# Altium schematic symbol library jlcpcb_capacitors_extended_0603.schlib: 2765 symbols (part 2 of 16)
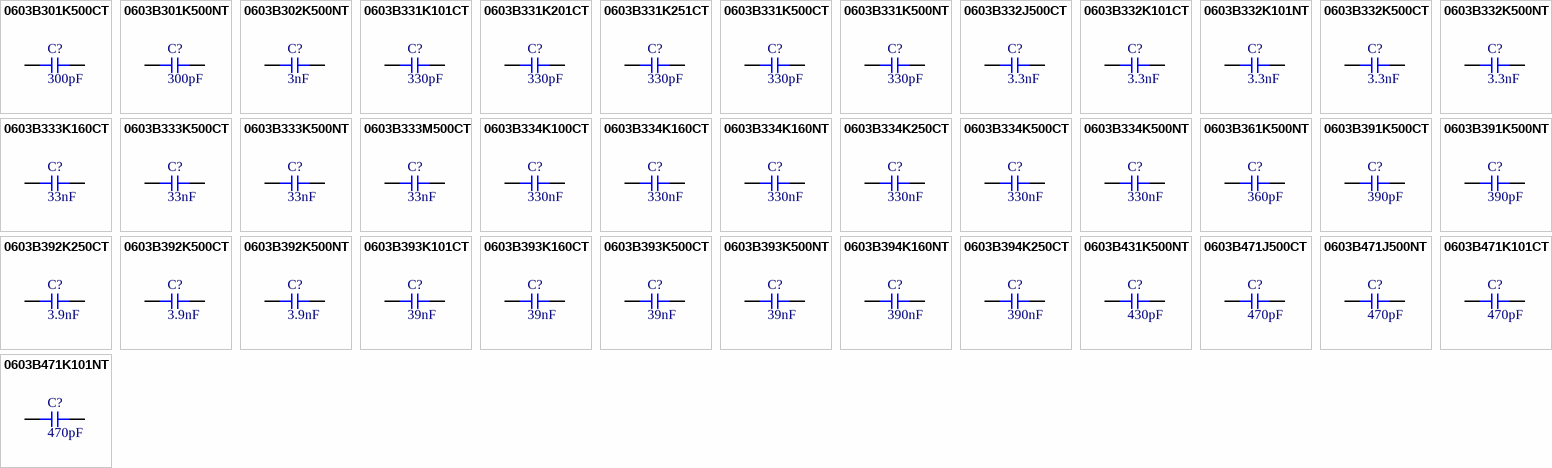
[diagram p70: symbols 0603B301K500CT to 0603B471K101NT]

## 0603B334K250CT
designator C?  Capacitance: 330nF  (hidden comment: *)
Capacitor, Ceramic (MLCC), 330nF, ±10%, 25V, X7R, ±10%, SMD 0603; Manufacturer: Walsin Tech Corp; Manufacturer Part Number: 0603B334K250CT
footprint CAP-0603 (0603 (1608M) Capacitor)
pins: 1, 2

## 0603B334K500CT
designator C?  Capacitance: 330nF  (hidden comment: *)
Capacitor, Ceramic (MLCC), 330nF, ±10%, 50V, X7R, ±10%, SMD 0603; Manufacturer: Walsin Tech Corp; Manufacturer Part Number: 0603B334K500CT
footprint CAP-0603 (0603 (1608M) Capacitor)
pins: 1, 2

## 0603B334K500NT
designator C?  Capacitance: 330nF  (hidden comment: *)
Capacitor, Ceramic (MLCC), 330nF, ±10%, 50V, X7R, ±10%, SMD 0603; Manufacturer: FH(Guangdong Fenghua Advanced Tech); Manufacturer Part Number: 0603B334K500NT
footprint CAP-0603 (0603 (1608M) Capacitor)
pins: 1, 2

## 0603B361K500NT
designator C?  Capacitance: 360pF  (hidden comment: *)
Capacitor, Ceramic (MLCC), 360pF, ±10%, 50V, X7R, ±10%, SMD 0603; Manufacturer: FH(Guangdong Fenghua Advanced Tech); Manufacturer Part Number: 0603B361K500NT
footprint CAP-0603 (0603 (1608M) Capacitor)
pins: 1, 2

## 0603B391K500CT
designator C?  Capacitance: 390pF  (hidden comment: *)
Capacitor, Ceramic (MLCC), 390pF, ±10%, 50V, X7R, ±10%, SMD 0603; Manufacturer: Walsin Tech Corp; Manufacturer Part Number: 0603B391K500CT
footprint CAP-0603 (0603 (1608M) Capacitor)
pins: 1, 2

## 0603B391K500NT
designator C?  Capacitance: 390pF  (hidden comment: *)
Capacitor, Ceramic (MLCC), 390pF, ±10%, 50V, X7R, ±10%, SMD 0603; Manufacturer: FH(Guangdong Fenghua Advanced Tech); Manufacturer Part Number: 0603B391K500NT
footprint CAP-0603 (0603 (1608M) Capacitor)
pins: 1, 2

## 0603B392K250CT
designator C?  Capacitance: 3.9nF  (hidden comment: *)
Capacitor, Ceramic (MLCC), 3.9nF, ±10%, 25V, X7R, ±10%, SMD 0603; Manufacturer: Walsin Tech Corp; Manufacturer Part Number: 0603B392K250CT
footprint CAP-0603 (0603 (1608M) Capacitor)
pins: 1, 2

## 0603B392K500CT
designator C?  Capacitance: 3.9nF  (hidden comment: *)
Capacitor, Ceramic (MLCC), 3.9nF, ±10%, 50V, X7R, ±10%, SMD 0603; Manufacturer: Walsin Tech Corp; Manufacturer Part Number: 0603B392K500CT
footprint CAP-0603 (0603 (1608M) Capacitor)
pins: 1, 2

## 0603B392K500NT
designator C?  Capacitance: 3.9nF  (hidden comment: *)
Capacitor, Ceramic (MLCC), 3.9nF, ±10%, 50V, X7R, ±10%, SMD 0603; Manufacturer: FH(Guangdong Fenghua Advanced Tech); Manufacturer Part Number: 0603B392K500NT
footprint CAP-0603 (0603 (1608M) Capacitor)
pins: 1, 2

## 0603B393K101CT
designator C?  Capacitance: 39nF  (hidden comment: *)
Capacitor, Ceramic (MLCC), 39nF, ±10%, 100V, X7R, ±10%, SMD 0603; Manufacturer: Walsin Tech Corp; Manufacturer Part Number: 0603B393K101CT
footprint CAP-0603 (0603 (1608M) Capacitor)
pins: 1, 2

## 0603B393K160CT
designator C?  Capacitance: 39nF  (hidden comment: *)
Capacitor, Ceramic (MLCC), 39nF, ±10%, 16V, X7R, ±10%, SMD 0603; Manufacturer: Walsin Tech Corp; Manufacturer Part Number: 0603B393K160CT
footprint CAP-0603 (0603 (1608M) Capacitor)
pins: 1, 2

## 0603B393K500CT
designator C?  Capacitance: 39nF  (hidden comment: *)
Capacitor, Ceramic (MLCC), 39nF, ±10%, 50V, X7R, ±10%, SMD 0603; Manufacturer: Walsin Tech Corp; Manufacturer Part Number: 0603B393K500CT
footprint CAP-0603 (0603 (1608M) Capacitor)
pins: 1, 2

## 0603B393K500NT
designator C?  Capacitance: 39nF  (hidden comment: *)
Capacitor, Ceramic (MLCC), 39nF, ±10%, 50V, X7R, ±10%, SMD 0603; Manufacturer: FH(Guangdong Fenghua Advanced Tech); Manufacturer Part Number: 0603B393K500NT
footprint CAP-0603 (0603 (1608M) Capacitor)
pins: 1, 2

## 0603B394K160NT
designator C?  Capacitance: 390nF  (hidden comment: *)
Capacitor, Ceramic (MLCC), 390nF, ±10%, 16V, ±10%, SMD 0603; Manufacturer: FH(Guangdong Fenghua Advanced Tech); Manufacturer Part Number: 0603B394K160NT
footprint CAP-0603 (0603 (1608M) Capacitor)
pins: 1, 2

## 0603B394K250CT
designator C?  Capacitance: 390nF  (hidden comment: *)
Capacitor, Ceramic (MLCC), 390nF, ±10%, 25V, X7R, ±10%, SMD 0603; Manufacturer: Walsin Tech Corp; Manufacturer Part Number: 0603B394K250CT
footprint CAP-0603 (0603 (1608M) Capacitor)
pins: 1, 2

## 0603B431K500NT
designator C?  Capacitance: 430pF  (hidden comment: *)
Capacitor, Ceramic (MLCC), 430pF, ±10%, 50V, X7R, ±10%, SMD 0603; Manufacturer: FH(Guangdong Fenghua Advanced Tech); Manufacturer Part Number: 0603B431K500NT
footprint CAP-0603 (0603 (1608M) Capacitor)
pins: 1, 2

## 0603B471J500CT
designator C?  Capacitance: 470pF  (hidden comment: *)
Capacitor, Ceramic (MLCC), 470pF, ±5%, 50V, X7R, ±5%, SMD 0603; Manufacturer: Walsin Tech Corp; Manufacturer Part Number: 0603B471J500CT
footprint CAP-0603 (0603 (1608M) Capacitor)
pins: 1, 2

## 0603B471J500NT
designator C?  Capacitance: 470pF  (hidden comment: *)
Capacitor, Ceramic (MLCC), 470pF, ±5%, 50V, X7R, ±5%, SMD 0603; Manufacturer: FH(Guangdong Fenghua Advanced Tech); Manufacturer Part Number: 0603B471J500NT
footprint CAP-0603 (0603 (1608M) Capacitor)
pins: 1, 2

## 0603B471K101CT
designator C?  Capacitance: 470pF  (hidden comment: *)
Capacitor, Ceramic (MLCC), 470pF, ±10%, 100V, X7R, ±10%, SMD 0603; Manufacturer: Walsin Tech Corp; Manufacturer Part Number: 0603B471K101CT
footprint CAP-0603 (0603 (1608M) Capacitor)
pins: 1, 2

## 0603B471K101NT
designator C?  Capacitance: 470pF  (hidden comment: *)
Capacitor, Ceramic (MLCC), 470pF, ±10%, 100V, X7R, ±10%, SMD 0603; Manufacturer: FH(Guangdong Fenghua Advanced Tech); Manufacturer Part Number: 0603B471K101NT
footprint CAP-0603 (0603 (1608M) Capacitor)
pins: 1, 2

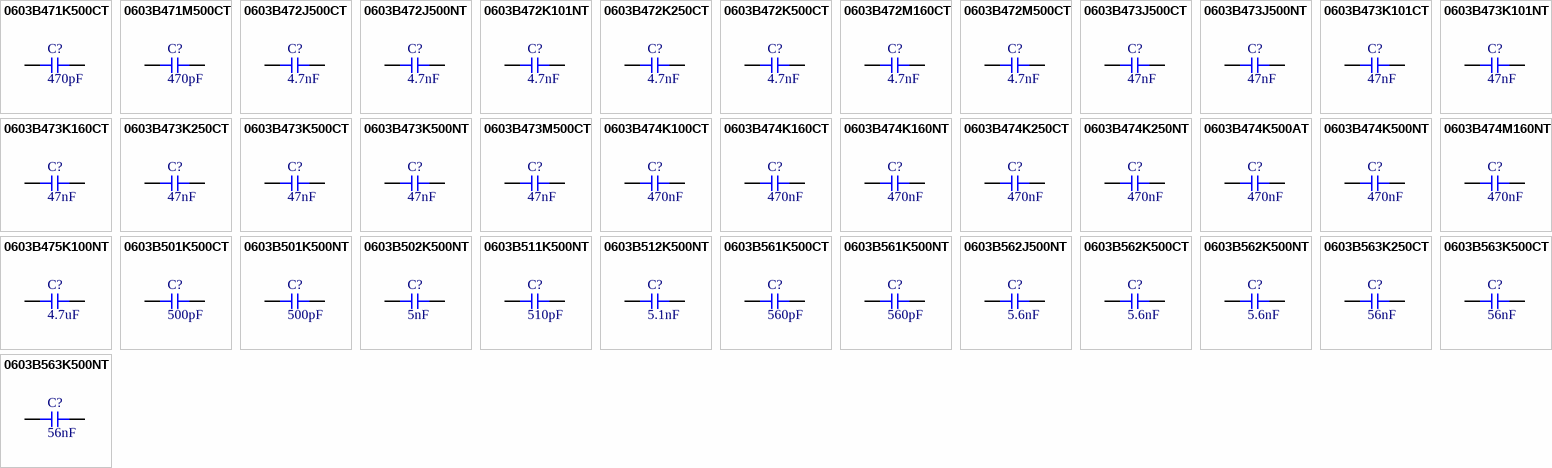
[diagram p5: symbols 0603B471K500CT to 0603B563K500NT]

## 0603B471K500CT
designator C?  Capacitance: 470pF  (hidden comment: *)
Capacitor, Ceramic (MLCC), 470pF, ±10%, 50V, X7R, ±10%, SMD 0603; Manufacturer: Walsin Tech Corp; Manufacturer Part Number: 0603B471K500CT
footprint CAP-0603 (0603 (1608M) Capacitor)
pins: 1, 2

## 0603B471M500CT
designator C?  Capacitance: 470pF  (hidden comment: *)
Capacitor, Ceramic (MLCC), 470pF, ±20%, 50V, X7R, ±20%, SMD 0603; Manufacturer: Walsin Tech Corp; Manufacturer Part Number: 0603B471M500CT
footprint CAP-0603 (0603 (1608M) Capacitor)
pins: 1, 2

## 0603B472J500CT
designator C?  Capacitance: 4.7nF  (hidden comment: *)
Capacitor, Ceramic (MLCC), 4.7nF, ±5%, 50V, X7R, ±5%, SMD 0603; Manufacturer: Walsin Tech Corp; Manufacturer Part Number: 0603B472J500CT
footprint CAP-0603 (0603 (1608M) Capacitor)
pins: 1, 2

## 0603B472J500NT
designator C?  Capacitance: 4.7nF  (hidden comment: *)
Capacitor, Ceramic (MLCC), 4.7nF, ±5%, 50V, X7R, ±5%, SMD 0603; Manufacturer: FH(Guangdong Fenghua Advanced Tech); Manufacturer Part Number: 0603B472J500NT
footprint CAP-0603 (0603 (1608M) Capacitor)
pins: 1, 2

## 0603B472K101NT
designator C?  Capacitance: 4.7nF  (hidden comment: *)
Capacitor, Ceramic (MLCC), 4.7nF, ±10%, 100V, X7R, ±10%, SMD 0603; Manufacturer: FH(Guangdong Fenghua Advanced Tech); Manufacturer Part Number: 0603B472K101NT
footprint CAP-0603 (0603 (1608M) Capacitor)
pins: 1, 2

## 0603B472K250CT
designator C?  Capacitance: 4.7nF  (hidden comment: *)
Capacitor, Ceramic (MLCC), 4.7nF, ±10%, 25V, X7R, ±10%, SMD 0603; Manufacturer: Walsin Tech Corp; Manufacturer Part Number: 0603B472K250CT
footprint CAP-0603 (0603 (1608M) Capacitor)
pins: 1, 2

## 0603B472K500CT
designator C?  Capacitance: 4.7nF  (hidden comment: *)
Capacitor, Ceramic (MLCC), 4.7nF, ±10%, 50V, X7R, ±10%, SMD 0603; Manufacturer: Walsin Tech Corp; Manufacturer Part Number: 0603B472K500CT
footprint CAP-0603 (0603 (1608M) Capacitor)
pins: 1, 2

## 0603B472M160CT
designator C?  Capacitance: 4.7nF  (hidden comment: *)
Capacitor, Ceramic (MLCC), 4.7nF, ±20%, 16V, X7R, ±20%, SMD 0603; Manufacturer: Walsin Tech Corp; Manufacturer Part Number: 0603B472M160CT
footprint CAP-0603 (0603 (1608M) Capacitor)
pins: 1, 2

## 0603B472M500CT
designator C?  Capacitance: 4.7nF  (hidden comment: *)
Capacitor, Ceramic (MLCC), 4.7nF, ±20%, 50V, X7R, ±20%, SMD 0603; Manufacturer: Walsin Tech Corp; Manufacturer Part Number: 0603B472M500CT
footprint CAP-0603 (0603 (1608M) Capacitor)
pins: 1, 2

## 0603B473J500CT
designator C?  Capacitance: 47nF  (hidden comment: *)
Capacitor, Ceramic (MLCC), 47nF, ±5%, 50V, X7R, ±5%, SMD 0603; Manufacturer: Walsin Tech Corp; Manufacturer Part Number: 0603B473J500CT
footprint CAP-0603 (0603 (1608M) Capacitor)
pins: 1, 2

## 0603B473J500NT
designator C?  Capacitance: 47nF  (hidden comment: *)
Capacitor, Ceramic (MLCC), 47nF, ±5%, 50V, X7R, ±5%, SMD 0603; Manufacturer: FH(Guangdong Fenghua Advanced Tech); Manufacturer Part Number: 0603B473J500NT
footprint CAP-0603 (0603 (1608M) Capacitor)
pins: 1, 2

## 0603B473K101CT
designator C?  Capacitance: 47nF  (hidden comment: *)
Capacitor, Ceramic (MLCC), 47nF, ±10%, 100V, X7R, ±10%, SMD 0603; Manufacturer: Walsin Tech Corp; Manufacturer Part Number: 0603B473K101CT
footprint CAP-0603 (0603 (1608M) Capacitor)
pins: 1, 2

## 0603B473K101NT
designator C?  Capacitance: 47nF  (hidden comment: *)
Capacitor, Ceramic (MLCC), 47nF, ±10%, 100V, X7R, ±10%, SMD 0603; Manufacturer: FH(Guangdong Fenghua Advanced Tech); Manufacturer Part Number: 0603B473K101NT
footprint CAP-0603 (0603 (1608M) Capacitor)
pins: 1, 2

## 0603B473K160CT
designator C?  Capacitance: 47nF  (hidden comment: *)
Capacitor, Ceramic (MLCC), 47nF, ±10%, 16V, X7R, ±10%, SMD 0603; Manufacturer: Walsin Tech Corp; Manufacturer Part Number: 0603B473K160CT
footprint CAP-0603 (0603 (1608M) Capacitor)
pins: 1, 2

## 0603B473K250CT
designator C?  Capacitance: 47nF  (hidden comment: *)
Capacitor, Ceramic (MLCC), 47nF, ±10%, 25V, X7R, ±10%, SMD 0603; Manufacturer: Walsin Tech Corp; Manufacturer Part Number: 0603B473K250CT
footprint CAP-0603 (0603 (1608M) Capacitor)
pins: 1, 2

## 0603B473K500CT
designator C?  Capacitance: 47nF  (hidden comment: *)
Capacitor, Ceramic (MLCC), 47nF, ±10%, 50V, X7R, ±10%, SMD 0603; Manufacturer: Walsin Tech Corp; Manufacturer Part Number: 0603B473K500CT
footprint CAP-0603 (0603 (1608M) Capacitor)
pins: 1, 2

## 0603B473K500NT
designator C?  Capacitance: 47nF  (hidden comment: *)
Capacitor, Ceramic (MLCC), 47nF, ±10%, 50V, X7R, ±10%, SMD 0603; Manufacturer: FH(Guangdong Fenghua Advanced Tech); Manufacturer Part Number: 0603B473K500NT
footprint CAP-0603 (0603 (1608M) Capacitor)
pins: 1, 2

## 0603B473M500CT
designator C?  Capacitance: 47nF  (hidden comment: *)
Capacitor, Ceramic (MLCC), 47nF, ±20%, 50V, X7R, ±20%, SMD 0603; Manufacturer: Walsin Tech Corp; Manufacturer Part Number: 0603B473M500CT
footprint CAP-0603 (0603 (1608M) Capacitor)
pins: 1, 2

## 0603B474K100CT
designator C?  Capacitance: 470nF  (hidden comment: *)
Capacitor, Ceramic (MLCC), 470nF, ±10%, 10V, X7R, ±10%, SMD 0603; Manufacturer: Walsin Tech Corp; Manufacturer Part Number: 0603B474K100CT
footprint CAP-0603 (0603 (1608M) Capacitor)
pins: 1, 2

## 0603B474K160CT
designator C?  Capacitance: 470nF  (hidden comment: *)
Capacitor, Ceramic (MLCC), 470nF, ±10%, 16V, X7R, ±10%, SMD 0603; Manufacturer: Walsin Tech Corp; Manufacturer Part Number: 0603B474K160CT
footprint CAP-0603 (0603 (1608M) Capacitor)
pins: 1, 2

## 0603B474K160NT
designator C?  Capacitance: 470nF  (hidden comment: *)
Capacitor, Ceramic (MLCC), 470nF, ±10%, 16V, X7R, ±10%, SMD 0603; Manufacturer: FH(Guangdong Fenghua Advanced Tech); Manufacturer Part Number: 0603B474K160NT
footprint CAP-0603 (0603 (1608M) Capacitor)
pins: 1, 2

## 0603B474K250CT
designator C?  Capacitance: 470nF  (hidden comment: *)
Capacitor, Ceramic (MLCC), 470nF, ±10%, 25V, X7R, ±10%, SMD 0603; Manufacturer: Walsin Tech Corp; Manufacturer Part Number: 0603B474K250CT
footprint CAP-0603 (0603 (1608M) Capacitor)
pins: 1, 2

## 0603B474K250NT
designator C?  Capacitance: 470nF  (hidden comment: *)
Capacitor, Ceramic (MLCC), 470nF, ±10%, 25V, X7R, ±10%, SMD 0603; Manufacturer: FH(Guangdong Fenghua Advanced Tech); Manufacturer Part Number: 0603B474K250NT
footprint CAP-0603 (0603 (1608M) Capacitor)
pins: 1, 2

## 0603B474K500AT
designator C?  Capacitance: 470nF  (hidden comment: *)
Capacitor, Ceramic (MLCC), 470nF, ±10%, 50V, ±10%, SMD 0603; Manufacturer: FH(Guangdong Fenghua Advanced Tech); Manufacturer Part Number: 0603B474K500AT
footprint CAP-0603 (0603 (1608M) Capacitor)
pins: 1, 2

## 0603B474K500NT
designator C?  Capacitance: 470nF  (hidden comment: *)
Capacitor, Ceramic (MLCC), 470nF, ±10%, 50V, X7R, ±10%, SMD 0603; Manufacturer: FH(Guangdong Fenghua Advanced Tech); Manufacturer Part Number: 0603B474K500NT
footprint CAP-0603 (0603 (1608M) Capacitor)
pins: 1, 2

## 0603B474M160NT
designator C?  Capacitance: 470nF  (hidden comment: *)
Capacitor, Ceramic (MLCC), 470nF, ±20%, 16V, X7R, ±20%, SMD 0603; Manufacturer: FH(Guangdong Fenghua Advanced Tech); Manufacturer Part Number: 0603B474M160NT
footprint CAP-0603 (0603 (1608M) Capacitor)
pins: 1, 2

## 0603B475K100NT
designator C?  Capacitance: 4.7uF  (hidden comment: *)
Capacitor, Ceramic (MLCC), 4.7uF, ±10%, 10V, X7R, ±10%, SMD 0603; Manufacturer: FH(Guangdong Fenghua Advanced Tech); Manufacturer Part Number: 0603B475K100NT
footprint CAP-0603 (0603 (1608M) Capacitor)
pins: 1, 2

## 0603B501K500CT
designator C?  Capacitance: 500pF  (hidden comment: *)
Capacitor, Ceramic (MLCC), 500pF, ±10%, 50V, X7R, ±10%, SMD 0603; Manufacturer: Walsin Tech Corp; Manufacturer Part Number: 0603B501K500CT
footprint CAP-0603 (0603 (1608M) Capacitor)
pins: 1, 2

## 0603B501K500NT
designator C?  Capacitance: 500pF  (hidden comment: *)
Capacitor, Ceramic (MLCC), 500pF, ±10%, 50V, X7R, ±10%, SMD 0603; Manufacturer: FH(Guangdong Fenghua Advanced Tech); Manufacturer Part Number: 0603B501K500NT
footprint CAP-0603 (0603 (1608M) Capacitor)
pins: 1, 2

## 0603B502K500NT
designator C?  Capacitance: 5nF  (hidden comment: *)
Capacitor, Ceramic (MLCC), 5nF, ±10%, 50V, X7R, ±10%, SMD 0603; Manufacturer: FH(Guangdong Fenghua Advanced Tech); Manufacturer Part Number: 0603B502K500NT
footprint CAP-0603 (0603 (1608M) Capacitor)
pins: 1, 2

## 0603B511K500NT
designator C?  Capacitance: 510pF  (hidden comment: *)
Capacitor, Ceramic (MLCC), 510pF, ±10%, 50V, X7R, ±10%, SMD 0603; Manufacturer: FH(Guangdong Fenghua Advanced Tech); Manufacturer Part Number: 0603B511K500NT
footprint CAP-0603 (0603 (1608M) Capacitor)
pins: 1, 2

## 0603B512K500NT
designator C?  Capacitance: 5.1nF  (hidden comment: *)
Capacitor, Ceramic (MLCC), 5.1nF, ±10%, 50V, X7R, ±10%, SMD 0603; Manufacturer: FH(Guangdong Fenghua Advanced Tech); Manufacturer Part Number: 0603B512K500NT
footprint CAP-0603 (0603 (1608M) Capacitor)
pins: 1, 2

## 0603B561K500CT
designator C?  Capacitance: 560pF  (hidden comment: *)
Capacitor, Ceramic (MLCC), 560pF, ±10%, 50V, X7R, ±10%, SMD 0603; Manufacturer: Walsin Tech Corp; Manufacturer Part Number: 0603B561K500CT
footprint CAP-0603 (0603 (1608M) Capacitor)
pins: 1, 2

## 0603B561K500NT
designator C?  Capacitance: 560pF  (hidden comment: *)
Capacitor, Ceramic (MLCC), 560pF, ±10%, 50V, X7R, ±10%, SMD 0603; Manufacturer: FH(Guangdong Fenghua Advanced Tech); Manufacturer Part Number: 0603B561K500NT
footprint CAP-0603 (0603 (1608M) Capacitor)
pins: 1, 2

## 0603B562J500NT
designator C?  Capacitance: 5.6nF  (hidden comment: *)
Capacitor, Ceramic (MLCC), 5.6nF, ±5%, 50V, X7R, ±5%, SMD 0603; Manufacturer: FH(Guangdong Fenghua Advanced Tech); Manufacturer Part Number: 0603B562J500NT
footprint CAP-0603 (0603 (1608M) Capacitor)
pins: 1, 2

## 0603B562K500CT
designator C?  Capacitance: 5.6nF  (hidden comment: *)
Capacitor, Ceramic (MLCC), 5.6nF, ±10%, 50V, X7R, ±10%, SMD 0603; Manufacturer: Walsin Tech Corp; Manufacturer Part Number: 0603B562K500CT
footprint CAP-0603 (0603 (1608M) Capacitor)
pins: 1, 2

## 0603B562K500NT
designator C?  Capacitance: 5.6nF  (hidden comment: *)
Capacitor, Ceramic (MLCC), 5.6nF, ±10%, 50V, X7R, ±10%, SMD 0603; Manufacturer: FH(Guangdong Fenghua Advanced Tech); Manufacturer Part Number: 0603B562K500NT
footprint CAP-0603 (0603 (1608M) Capacitor)
pins: 1, 2

## 0603B563K250CT
designator C?  Capacitance: 56nF  (hidden comment: *)
Capacitor, Ceramic (MLCC), 56nF, ±10%, 25V, X7R, ±10%, SMD 0603; Manufacturer: Walsin Tech Corp; Manufacturer Part Number: 0603B563K250CT
footprint CAP-0603 (0603 (1608M) Capacitor)
pins: 1, 2

## 0603B563K500CT
designator C?  Capacitance: 56nF  (hidden comment: *)
Capacitor, Ceramic (MLCC), 56nF, ±10%, 50V, X7R, ±10%, SMD 0603; Manufacturer: Walsin Tech Corp; Manufacturer Part Number: 0603B563K500CT
footprint CAP-0603 (0603 (1608M) Capacitor)
pins: 1, 2

## 0603B563K500NT
designator C?  Capacitance: 56nF  (hidden comment: *)
Capacitor, Ceramic (MLCC), 56nF, ±10%, 50V, X7R, ±10%, SMD 0603; Manufacturer: FH(Guangdong Fenghua Advanced Tech); Manufacturer Part Number: 0603B563K500NT
footprint CAP-0603 (0603 (1608M) Capacitor)
pins: 1, 2

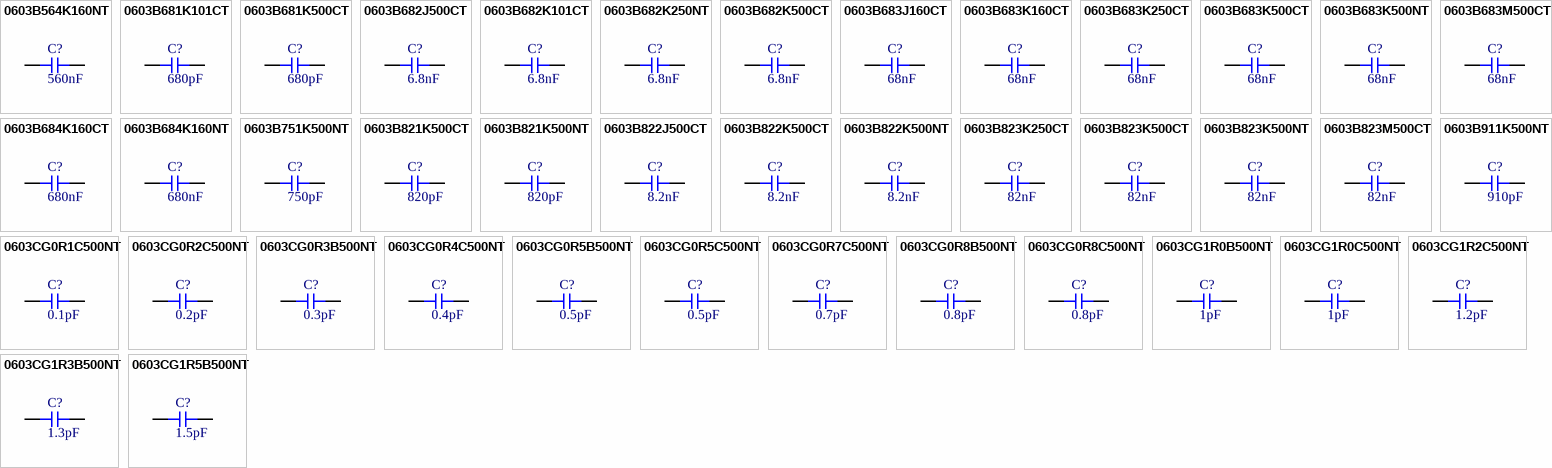
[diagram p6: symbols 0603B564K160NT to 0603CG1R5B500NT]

## 0603B564K160NT
designator C?  Capacitance: 560nF  (hidden comment: *)
Capacitor, Ceramic (MLCC), 560nF, ±10%, 16V, ±10%, SMD 0603; Manufacturer: FH(Guangdong Fenghua Advanced Tech); Manufacturer Part Number: 0603B564K160NT
footprint CAP-0603 (0603 (1608M) Capacitor)
pins: 1, 2

## 0603B681K101CT
designator C?  Capacitance: 680pF  (hidden comment: *)
Capacitor, Ceramic (MLCC), 680pF, ±10%, 100V, X7R, ±10%, SMD 0603; Manufacturer: Walsin Tech Corp; Manufacturer Part Number: 0603B681K101CT
footprint CAP-0603 (0603 (1608M) Capacitor)
pins: 1, 2

## 0603B681K500CT
designator C?  Capacitance: 680pF  (hidden comment: *)
Capacitor, Ceramic (MLCC), 680pF, ±10%, 50V, X7R, ±10%, SMD 0603; Manufacturer: Walsin Tech Corp; Manufacturer Part Number: 0603B681K500CT
footprint CAP-0603 (0603 (1608M) Capacitor)
pins: 1, 2

## 0603B682J500CT
designator C?  Capacitance: 6.8nF  (hidden comment: *)
Capacitor, Ceramic (MLCC), 6.8nF, ±5%, 50V, X7R, ±5%, SMD 0603; Manufacturer: Walsin Tech Corp; Manufacturer Part Number: 0603B682J500CT
footprint CAP-0603 (0603 (1608M) Capacitor)
pins: 1, 2

## 0603B682K101CT
designator C?  Capacitance: 6.8nF  (hidden comment: *)
Capacitor, Ceramic (MLCC), 6.8nF, ±10%, 100V, X7R, ±10%, SMD 0603; Manufacturer: Walsin Tech Corp; Manufacturer Part Number: 0603B682K101CT
footprint CAP-0603 (0603 (1608M) Capacitor)
pins: 1, 2

## 0603B682K250NT
designator C?  Capacitance: 6.8nF  (hidden comment: *)
Capacitor, Ceramic (MLCC), 6.8nF, ±10%, 25V, X7R, ±10%, SMD 0603; Manufacturer: FH(Guangdong Fenghua Advanced Tech); Manufacturer Part Number: 0603B682K250NT
footprint CAP-0603 (0603 (1608M) Capacitor)
pins: 1, 2

## 0603B682K500CT
designator C?  Capacitance: 6.8nF  (hidden comment: *)
Capacitor, Ceramic (MLCC), 6.8nF, ±10%, 50V, X7R, ±10%, SMD 0603; Manufacturer: Walsin Tech Corp; Manufacturer Part Number: 0603B682K500CT
footprint CAP-0603 (0603 (1608M) Capacitor)
pins: 1, 2

## 0603B683J160CT
designator C?  Capacitance: 68nF  (hidden comment: *)
Capacitor, Ceramic (MLCC), 68nF, ±5%, 16V, X7R, ±5%, SMD 0603; Manufacturer: Walsin Tech Corp; Manufacturer Part Number: 0603B683J160CT
footprint CAP-0603 (0603 (1608M) Capacitor)
pins: 1, 2

## 0603B683K160CT
designator C?  Capacitance: 68nF  (hidden comment: *)
Capacitor, Ceramic (MLCC), 68nF, ±10%, 16V, X7R, ±10%, SMD 0603; Manufacturer: Walsin Tech Corp; Manufacturer Part Number: 0603B683K160CT
footprint CAP-0603 (0603 (1608M) Capacitor)
pins: 1, 2

## 0603B683K250CT
designator C?  Capacitance: 68nF  (hidden comment: *)
Capacitor, Ceramic (MLCC), 68nF, ±10%, 25V, X7R, ±10%, SMD 0603; Manufacturer: Walsin Tech Corp; Manufacturer Part Number: 0603B683K250CT
footprint CAP-0603 (0603 (1608M) Capacitor)
pins: 1, 2

## 0603B683K500CT
designator C?  Capacitance: 68nF  (hidden comment: *)
Capacitor, Ceramic (MLCC), 68nF, ±10%, 50V, X7R, ±10%, SMD 0603; Manufacturer: Walsin Tech Corp; Manufacturer Part Number: 0603B683K500CT
footprint CAP-0603 (0603 (1608M) Capacitor)
pins: 1, 2

## 0603B683K500NT
designator C?  Capacitance: 68nF  (hidden comment: *)
Capacitor, Ceramic (MLCC), 68nF, ±10%, 50V, X7R, ±10%, SMD 0603; Manufacturer: FH(Guangdong Fenghua Advanced Tech); Manufacturer Part Number: 0603B683K500NT
footprint CAP-0603 (0603 (1608M) Capacitor)
pins: 1, 2

## 0603B683M500CT
designator C?  Capacitance: 68nF  (hidden comment: *)
Capacitor, Ceramic (MLCC), 68nF, ±20%, 50V, X7R, ±20%, SMD 0603; Manufacturer: Walsin Tech Corp; Manufacturer Part Number: 0603B683M500CT
footprint CAP-0603 (0603 (1608M) Capacitor)
pins: 1, 2

## 0603B684K160CT
designator C?  Capacitance: 680nF  (hidden comment: *)
Capacitor, Ceramic (MLCC), 680nF, ±10%, 16V, X7R, ±10%, SMD 0603; Manufacturer: Walsin Tech Corp; Manufacturer Part Number: 0603B684K160CT
footprint CAP-0603 (0603 (1608M) Capacitor)
pins: 1, 2

## 0603B684K160NT
designator C?  Capacitance: 680nF  (hidden comment: *)
Capacitor, Ceramic (MLCC), 680nF, ±10%, 16V, X7R, ±10%, SMD 0603; Manufacturer: FH(Guangdong Fenghua Advanced Tech); Manufacturer Part Number: 0603B684K160NT
footprint CAP-0603 (0603 (1608M) Capacitor)
pins: 1, 2

## 0603B751K500NT
designator C?  Capacitance: 750pF  (hidden comment: *)
Capacitor, Ceramic (MLCC), 750pF, ±10%, 50V, X7R, ±10%, SMD 0603; Manufacturer: FH(Guangdong Fenghua Advanced Tech); Manufacturer Part Number: 0603B751K500NT
footprint CAP-0603 (0603 (1608M) Capacitor)
pins: 1, 2

## 0603B821K500CT
designator C?  Capacitance: 820pF  (hidden comment: *)
Capacitor, Ceramic (MLCC), 820pF, ±10%, 50V, X7R, ±10%, SMD 0603; Manufacturer: Walsin Tech Corp; Manufacturer Part Number: 0603B821K500CT
footprint CAP-0603 (0603 (1608M) Capacitor)
pins: 1, 2

## 0603B821K500NT
designator C?  Capacitance: 820pF  (hidden comment: *)
Capacitor, Ceramic (MLCC), 820pF, ±10%, 50V, X7R, ±10%, SMD 0603; Manufacturer: FH(Guangdong Fenghua Advanced Tech); Manufacturer Part Number: 0603B821K500NT
footprint CAP-0603 (0603 (1608M) Capacitor)
pins: 1, 2

## 0603B822J500CT
designator C?  Capacitance: 8.2nF  (hidden comment: *)
Capacitor, Ceramic (MLCC), 8.2nF, ±5%, 50V, X7R, ±5%, SMD 0603; Manufacturer: Walsin Tech Corp; Manufacturer Part Number: 0603B822J500CT
footprint CAP-0603 (0603 (1608M) Capacitor)
pins: 1, 2

## 0603B822K500CT
designator C?  Capacitance: 8.2nF  (hidden comment: *)
Capacitor, Ceramic (MLCC), 8.2nF, ±10%, 50V, X7R, ±10%, SMD 0603; Manufacturer: Walsin Tech Corp; Manufacturer Part Number: 0603B822K500CT
footprint CAP-0603 (0603 (1608M) Capacitor)
pins: 1, 2

## 0603B822K500NT
designator C?  Capacitance: 8.2nF  (hidden comment: *)
Capacitor, Ceramic (MLCC), 8.2nF, ±10%, 50V, ±10%, SMD 0603; Manufacturer: FH(Guangdong Fenghua Advanced Tech); Manufacturer Part Number: 0603B822K500NT
footprint CAP-0603 (0603 (1608M) Capacitor)
pins: 1, 2

## 0603B823K250CT
designator C?  Capacitance: 82nF  (hidden comment: *)
Capacitor, Ceramic (MLCC), 82nF, ±10%, 25V, X7R, ±10%, SMD 0603; Manufacturer: Walsin Tech Corp; Manufacturer Part Number: 0603B823K250CT
footprint CAP-0603 (0603 (1608M) Capacitor)
pins: 1, 2

## 0603B823K500CT
designator C?  Capacitance: 82nF  (hidden comment: *)
Capacitor, Ceramic (MLCC), 82nF, ±10%, 50V, X7R, ±10%, SMD 0603; Manufacturer: Walsin Tech Corp; Manufacturer Part Number: 0603B823K500CT
footprint CAP-0603 (0603 (1608M) Capacitor)
pins: 1, 2

## 0603B823K500NT
designator C?  Capacitance: 82nF  (hidden comment: *)
Capacitor, Ceramic (MLCC), 82nF, ±10%, 50V, X7R, ±10%, SMD 0603; Manufacturer: FH(Guangdong Fenghua Advanced Tech); Manufacturer Part Number: 0603B823K500NT
footprint CAP-0603 (0603 (1608M) Capacitor)
pins: 1, 2

## 0603B823M500CT
designator C?  Capacitance: 82nF  (hidden comment: *)
Capacitor, Ceramic (MLCC), 82nF, ±20%, 50V, X7R, ±20%, SMD 0603; Manufacturer: Walsin Tech Corp; Manufacturer Part Number: 0603B823M500CT
footprint CAP-0603 (0603 (1608M) Capacitor)
pins: 1, 2

## 0603B911K500NT
designator C?  Capacitance: 910pF  (hidden comment: *)
Capacitor, Ceramic (MLCC), 910pF, ±10%, 50V, X7R, ±10%, SMD 0603; Manufacturer: FH(Guangdong Fenghua Advanced Tech); Manufacturer Part Number: 0603B911K500NT
footprint CAP-0603 (0603 (1608M) Capacitor)
pins: 1, 2

## 0603CG0R1C500NT
designator C?  Capacitance: 0.1pF  (hidden comment: *)
Capacitor, Ceramic (MLCC), 0.1pF, ±0.25pF, 50V, ±0.25pF, SMD 0603; Manufacturer: FH(Guangdong Fenghua Advanced Tech); Manufacturer Part Number: 0603CG0R1C500NT
footprint CAP-0603 (0603 (1608M) Capacitor)
pins: 1, 2

## 0603CG0R2C500NT
designator C?  Capacitance: 0.2pF  (hidden comment: *)
Capacitor, Ceramic (MLCC), 0.2pF, ±0.25pF, 50V, C0G, ±0.25pF, SMD 0603; Manufacturer: FH(Guangdong Fenghua Advanced Tech); Manufacturer Part Number: 0603CG0R2C500NT
footprint CAP-0603 (0603 (1608M) Capacitor)
pins: 1, 2

## 0603CG0R3B500NT
designator C?  Capacitance: 0.3pF  (hidden comment: *)
Capacitor, Ceramic (MLCC), 0.3pF, ±0.1pF, 50V, C0G, ±0.1pF, SMD 0603; Manufacturer: FH(Guangdong Fenghua Advanced Tech); Manufacturer Part Number: 0603CG0R3B500NT
footprint CAP-0603 (0603 (1608M) Capacitor)
pins: 1, 2

## 0603CG0R4C500NT
designator C?  Capacitance: 0.4pF  (hidden comment: *)
Capacitor, Ceramic (MLCC), 0.4pF, ±0.25pF, 50V, C0G, ±0.25pF, SMD 0603; Manufacturer: FH(Guangdong Fenghua Advanced Tech); Manufacturer Part Number: 0603CG0R4C500NT
footprint CAP-0603 (0603 (1608M) Capacitor)
pins: 1, 2

## 0603CG0R5B500NT
designator C?  Capacitance: 0.5pF  (hidden comment: *)
Capacitor, Ceramic (MLCC), 0.5pF, ±0.1pF, 50V, C0G, ±0.1pF, SMD 0603; Manufacturer: FH(Guangdong Fenghua Advanced Tech); Manufacturer Part Number: 0603CG0R5B500NT
footprint CAP-0603 (0603 (1608M) Capacitor)
pins: 1, 2

## 0603CG0R5C500NT
designator C?  Capacitance: 0.5pF  (hidden comment: *)
Capacitor, Ceramic (MLCC), 0.5pF, ±0.25pF, 50V, C0G, ±0.25pF, SMD 0603; Manufacturer: FH(Guangdong Fenghua Advanced Tech); Manufacturer Part Number: 0603CG0R5C500NT
footprint CAP-0603 (0603 (1608M) Capacitor)
pins: 1, 2

## 0603CG0R7C500NT
designator C?  Capacitance: 0.7pF  (hidden comment: *)
Capacitor, Ceramic (MLCC), 0.7pF, ±0.25pF, 50V, C0G, ±0.25pF, SMD 0603; Manufacturer: FH(Guangdong Fenghua Advanced Tech); Manufacturer Part Number: 0603CG0R7C500NT
footprint CAP-0603 (0603 (1608M) Capacitor)
pins: 1, 2

## 0603CG0R8B500NT
designator C?  Capacitance: 0.8pF  (hidden comment: *)
Capacitor, Ceramic (MLCC), 0.8pF, ±0.1pF, 50V, C0G, ±0.1pF, SMD 0603; Manufacturer: FH(Guangdong Fenghua Advanced Tech); Manufacturer Part Number: 0603CG0R8B500NT
footprint CAP-0603 (0603 (1608M) Capacitor)
pins: 1, 2

## 0603CG0R8C500NT
designator C?  Capacitance: 0.8pF  (hidden comment: *)
Capacitor, Ceramic (MLCC), 0.8pF, ±0.25pF, 50V, C0G, ±0.25pF, SMD 0603; Manufacturer: FH(Guangdong Fenghua Advanced Tech); Manufacturer Part Number: 0603CG0R8C500NT
footprint CAP-0603 (0603 (1608M) Capacitor)
pins: 1, 2

## 0603CG1R0B500NT
designator C?  Capacitance: 1pF  (hidden comment: *)
Capacitor, Ceramic (MLCC), 1pF, ±0.1pF, 50V, C0G, ±0.1pF, SMD 0603; Manufacturer: FH(Guangdong Fenghua Advanced Tech); Manufacturer Part Number: 0603CG1R0B500NT
footprint CAP-0603 (0603 (1608M) Capacitor)
pins: 1, 2

## 0603CG1R0C500NT
designator C?  Capacitance: 1pF  (hidden comment: *)
Capacitor, Ceramic (MLCC), 1pF, ±0.25pF, 50V, C0G, ±0.25pF, SMD 0603; Manufacturer: FH(Guangdong Fenghua Advanced Tech); Manufacturer Part Number: 0603CG1R0C500NT
footprint CAP-0603 (0603 (1608M) Capacitor)
pins: 1, 2

## 0603CG1R2C500NT
designator C?  Capacitance: 1.2pF  (hidden comment: *)
Capacitor, Ceramic (MLCC), 1.2pF, ±0.25pF, 50V, C0G, ±0.25pF, SMD 0603; Manufacturer: FH(Guangdong Fenghua Advanced Tech); Manufacturer Part Number: 0603CG1R2C500NT
footprint CAP-0603 (0603 (1608M) Capacitor)
pins: 1, 2

## 0603CG1R3B500NT
designator C?  Capacitance: 1.3pF  (hidden comment: *)
Capacitor, Ceramic (MLCC), 1.3pF, ±0.1pF, 50V, C0G, ±0.1pF, SMD 0603; Manufacturer: FH(Guangdong Fenghua Advanced Tech); Manufacturer Part Number: 0603CG1R3B500NT
footprint CAP-0603 (0603 (1608M) Capacitor)
pins: 1, 2

## 0603CG1R5B500NT
designator C?  Capacitance: 1.5pF  (hidden comment: *)
Capacitor, Ceramic (MLCC), 1.5pF, ±0.1pF, 50V, C0G, ±0.1pF, SMD 0603; Manufacturer: FH(Guangdong Fenghua Advanced Tech); Manufacturer Part Number: 0603CG1R5B500NT
footprint CAP-0603 (0603 (1608M) Capacitor)
pins: 1, 2

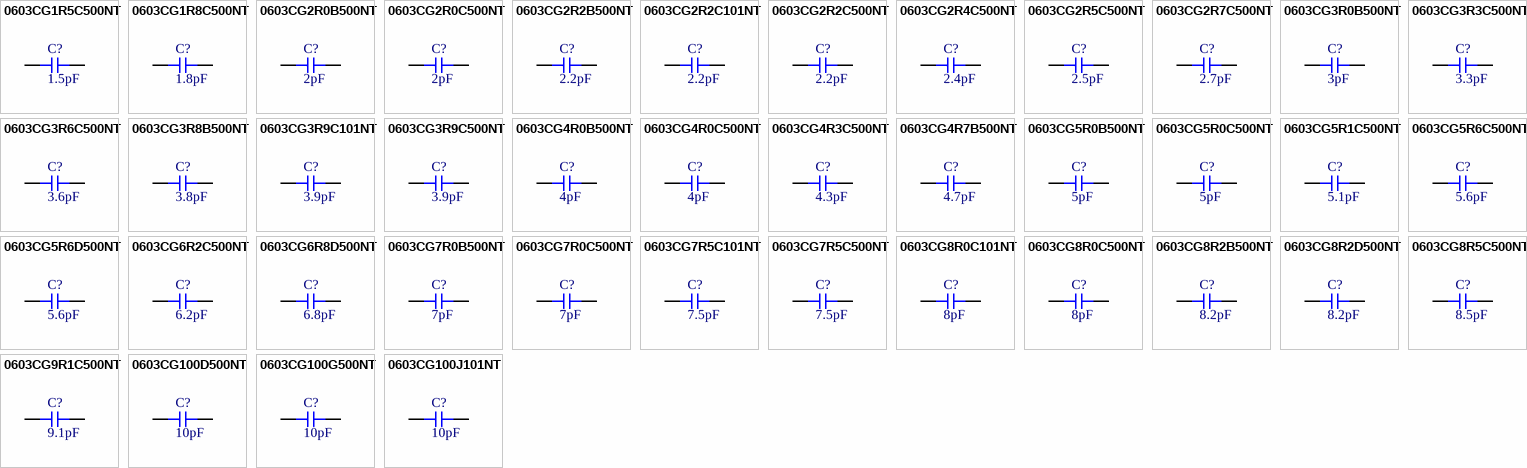
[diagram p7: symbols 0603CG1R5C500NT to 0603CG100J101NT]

## 0603CG1R5C500NT
designator C?  Capacitance: 1.5pF  (hidden comment: *)
Capacitor, Ceramic (MLCC), 1.5pF, ±0.25pF, 50V, C0G, ±0.25pF, SMD 0603; Manufacturer: FH(Guangdong Fenghua Advanced Tech); Manufacturer Part Number: 0603CG1R5C500NT
footprint CAP-0603 (0603 (1608M) Capacitor)
pins: 1, 2

## 0603CG1R8C500NT
designator C?  Capacitance: 1.8pF  (hidden comment: *)
Capacitor, Ceramic (MLCC), 1.8pF, ±0.25pF, 50V, C0G, ±0.25pF, SMD 0603; Manufacturer: FH(Guangdong Fenghua Advanced Tech); Manufacturer Part Number: 0603CG1R8C500NT
footprint CAP-0603 (0603 (1608M) Capacitor)
pins: 1, 2

## 0603CG2R0B500NT
designator C?  Capacitance: 2pF  (hidden comment: *)
Capacitor, Ceramic (MLCC), 2pF, ±0.1pF, 50V, C0G, ±0.1pF, SMD 0603; Manufacturer: FH(Guangdong Fenghua Advanced Tech); Manufacturer Part Number: 0603CG2R0B500NT
footprint CAP-0603 (0603 (1608M) Capacitor)
pins: 1, 2

## 0603CG2R0C500NT
designator C?  Capacitance: 2pF  (hidden comment: *)
Capacitor, Ceramic (MLCC), 2pF, ±0.25pF, 50V, C0G, ±0.25pF, SMD 0603; Manufacturer: FH(Guangdong Fenghua Advanced Tech); Manufacturer Part Number: 0603CG2R0C500NT
footprint CAP-0603 (0603 (1608M) Capacitor)
pins: 1, 2

## 0603CG2R2B500NT
designator C?  Capacitance: 2.2pF  (hidden comment: *)
Capacitor, Ceramic (MLCC), 2.2pF, ±0.1pF, 50V, C0G, ±0.1pF, SMD 0603; Manufacturer: FH(Guangdong Fenghua Advanced Tech); Manufacturer Part Number: 0603CG2R2B500NT
footprint CAP-0603 (0603 (1608M) Capacitor)
pins: 1, 2

## 0603CG2R2C101NT
designator C?  Capacitance: 2.2pF  (hidden comment: *)
Capacitor, Ceramic (MLCC), 2.2pF, ±0.25pF, 100V, C0G, ±0.25pF, SMD 0603; Manufacturer: FH(Guangdong Fenghua Advanced Tech); Manufacturer Part Number: 0603CG2R2C101NT
footprint CAP-0603 (0603 (1608M) Capacitor)
pins: 1, 2

## 0603CG2R2C500NT
designator C?  Capacitance: 2.2pF  (hidden comment: *)
Capacitor, Ceramic (MLCC), 2.2pF, ±0.25pF, 50V, C0G, ±0.25pF, SMD 0603; Manufacturer: FH(Guangdong Fenghua Advanced Tech); Manufacturer Part Number: 0603CG2R2C500NT
footprint CAP-0603 (0603 (1608M) Capacitor)
pins: 1, 2

## 0603CG2R4C500NT
designator C?  Capacitance: 2.4pF  (hidden comment: *)
Capacitor, Ceramic (MLCC), 2.4pF, ±0.25pF, 50V, C0G, ±0.25pF, SMD 0603; Manufacturer: FH(Guangdong Fenghua Advanced Tech); Manufacturer Part Number: 0603CG2R4C500NT
footprint CAP-0603 (0603 (1608M) Capacitor)
pins: 1, 2

## 0603CG2R5C500NT
designator C?  Capacitance: 2.5pF  (hidden comment: *)
Capacitor, Ceramic (MLCC), 2.5pF, ±0.25pF, 50V, C0G, ±0.25pF, SMD 0603; Manufacturer: FH(Guangdong Fenghua Advanced Tech); Manufacturer Part Number: 0603CG2R5C500NT
footprint CAP-0603 (0603 (1608M) Capacitor)
pins: 1, 2

## 0603CG2R7C500NT
designator C?  Capacitance: 2.7pF  (hidden comment: *)
Capacitor, Ceramic (MLCC), 2.7pF, ±0.25pF, 50V, C0G, ±0.25pF, SMD 0603; Manufacturer: FH(Guangdong Fenghua Advanced Tech); Manufacturer Part Number: 0603CG2R7C500NT
footprint CAP-0603 (0603 (1608M) Capacitor)
pins: 1, 2

## 0603CG3R0B500NT
designator C?  Capacitance: 3pF  (hidden comment: *)
Capacitor, Ceramic (MLCC), 3pF, ±0.1pF, 50V, C0G, ±0.1pF, SMD 0603; Manufacturer: FH(Guangdong Fenghua Advanced Tech); Manufacturer Part Number: 0603CG3R0B500NT
footprint CAP-0603 (0603 (1608M) Capacitor)
pins: 1, 2

## 0603CG3R3C500NT
designator C?  Capacitance: 3.3pF  (hidden comment: *)
Capacitor, Ceramic (MLCC), 3.3pF, ±0.25pF, 50V, C0G, ±0.25pF, SMD 0603; Manufacturer: FH(Guangdong Fenghua Advanced Tech); Manufacturer Part Number: 0603CG3R3C500NT
footprint CAP-0603 (0603 (1608M) Capacitor)
pins: 1, 2

## 0603CG3R6C500NT
designator C?  Capacitance: 3.6pF  (hidden comment: *)
Capacitor, Ceramic (MLCC), 3.6pF, ±0.25pF, 50V, C0G, ±0.25pF, SMD 0603; Manufacturer: FH(Guangdong Fenghua Advanced Tech); Manufacturer Part Number: 0603CG3R6C500NT
footprint CAP-0603 (0603 (1608M) Capacitor)
pins: 1, 2

## 0603CG3R8B500NT
designator C?  Capacitance: 3.8pF  (hidden comment: *)
Capacitor, Ceramic (MLCC), 3.8pF, ±0.1pF, 50V, C0G, ±0.1pF, SMD 0603; Manufacturer: FH(Guangdong Fenghua Advanced Tech); Manufacturer Part Number: 0603CG3R8B500NT
footprint CAP-0603 (0603 (1608M) Capacitor)
pins: 1, 2

## 0603CG3R9C101NT
designator C?  Capacitance: 3.9pF  (hidden comment: *)
Capacitor, Ceramic (MLCC), 3.9pF, ±0.25pF, 100V, C0G, ±0.25pF, SMD 0603; Manufacturer: FH(Guangdong Fenghua Advanced Tech); Manufacturer Part Number: 0603CG3R9C101NT
footprint CAP-0603 (0603 (1608M) Capacitor)
pins: 1, 2

## 0603CG3R9C500NT
designator C?  Capacitance: 3.9pF  (hidden comment: *)
Capacitor, Ceramic (MLCC), 3.9pF, ±0.25pF, 50V, C0G, ±0.25pF, SMD 0603; Manufacturer: FH(Guangdong Fenghua Advanced Tech); Manufacturer Part Number: 0603CG3R9C500NT
footprint CAP-0603 (0603 (1608M) Capacitor)
pins: 1, 2

## 0603CG4R0B500NT
designator C?  Capacitance: 4pF  (hidden comment: *)
Capacitor, Ceramic (MLCC), 4pF, ±0.1pF, 50V, C0G, ±0.1pF, SMD 0603; Manufacturer: FH(Guangdong Fenghua Advanced Tech); Manufacturer Part Number: 0603CG4R0B500NT
footprint CAP-0603 (0603 (1608M) Capacitor)
pins: 1, 2

## 0603CG4R0C500NT
designator C?  Capacitance: 4pF  (hidden comment: *)
Capacitor, Ceramic (MLCC), 4pF, ±0.25pF, 50V, C0G, ±0.25pF, SMD 0603; Manufacturer: FH(Guangdong Fenghua Advanced Tech); Manufacturer Part Number: 0603CG4R0C500NT
footprint CAP-0603 (0603 (1608M) Capacitor)
pins: 1, 2

## 0603CG4R3C500NT
designator C?  Capacitance: 4.3pF  (hidden comment: *)
Capacitor, Ceramic (MLCC), 4.3pF, ±0.25pF, 50V, C0G, ±0.25pF, SMD 0603; Manufacturer: FH(Guangdong Fenghua Advanced Tech); Manufacturer Part Number: 0603CG4R3C500NT
footprint CAP-0603 (0603 (1608M) Capacitor)
pins: 1, 2

## 0603CG4R7B500NT
designator C?  Capacitance: 4.7pF  (hidden comment: *)
Capacitor, Ceramic (MLCC), 4.7pF, ±0.1pF, 50V, C0G, ±0.1pF, SMD 0603; Manufacturer: FH(Guangdong Fenghua Advanced Tech); Manufacturer Part Number: 0603CG4R7B500NT
footprint CAP-0603 (0603 (1608M) Capacitor)
pins: 1, 2

## 0603CG5R0B500NT
designator C?  Capacitance: 5pF  (hidden comment: *)
Capacitor, Ceramic (MLCC), 5pF, ±0.1pF, 50V, C0G, ±0.1pF, SMD 0603; Manufacturer: FH(Guangdong Fenghua Advanced Tech); Manufacturer Part Number: 0603CG5R0B500NT
footprint CAP-0603 (0603 (1608M) Capacitor)
pins: 1, 2

## 0603CG5R0C500NT
designator C?  Capacitance: 5pF  (hidden comment: *)
Capacitor, Ceramic (MLCC), 5pF, ±0.25pF, 50V, C0G, ±0.25pF, SMD 0603; Manufacturer: FH(Guangdong Fenghua Advanced Tech); Manufacturer Part Number: 0603CG5R0C500NT
footprint CAP-0603 (0603 (1608M) Capacitor)
pins: 1, 2

## 0603CG5R1C500NT
designator C?  Capacitance: 5.1pF  (hidden comment: *)
Capacitor, Ceramic (MLCC), 5.1pF, ±0.25pF, 50V, C0G, ±0.25pF, SMD 0603; Manufacturer: FH(Guangdong Fenghua Advanced Tech); Manufacturer Part Number: 0603CG5R1C500NT
footprint CAP-0603 (0603 (1608M) Capacitor)
pins: 1, 2

## 0603CG5R6C500NT
designator C?  Capacitance: 5.6pF  (hidden comment: *)
Capacitor, Ceramic (MLCC), 5.6pF, ±0.25pF, 50V, C0G, ±0.25pF, SMD 0603; Manufacturer: FH(Guangdong Fenghua Advanced Tech); Manufacturer Part Number: 0603CG5R6C500NT
footprint CAP-0603 (0603 (1608M) Capacitor)
pins: 1, 2

## 0603CG5R6D500NT
designator C?  Capacitance: 5.6pF  (hidden comment: *)
Capacitor, Ceramic (MLCC), 5.6pF, ±0.5pF, 50V, C0G, ±0.5pF, SMD 0603; Manufacturer: FH(Guangdong Fenghua Advanced Tech); Manufacturer Part Number: 0603CG5R6D500NT
footprint CAP-0603 (0603 (1608M) Capacitor)
pins: 1, 2

## 0603CG6R2C500NT
designator C?  Capacitance: 6.2pF  (hidden comment: *)
Capacitor, Ceramic (MLCC), 6.2pF, ±0.25pF, 50V, C0G, ±0.25pF, SMD 0603; Manufacturer: FH(Guangdong Fenghua Advanced Tech); Manufacturer Part Number: 0603CG6R2C500NT
footprint CAP-0603 (0603 (1608M) Capacitor)
pins: 1, 2

## 0603CG6R8D500NT
designator C?  Capacitance: 6.8pF  (hidden comment: *)
Capacitor, Ceramic (MLCC), 6.8pF, ±0.5pF, 50V, C0G, ±0.5pF, SMD 0603; Manufacturer: FH(Guangdong Fenghua Advanced Tech); Manufacturer Part Number: 0603CG6R8D500NT
footprint CAP-0603 (0603 (1608M) Capacitor)
pins: 1, 2

## 0603CG7R0B500NT
designator C?  Capacitance: 7pF  (hidden comment: *)
Capacitor, Ceramic (MLCC), 7pF, ±0.1pF, 50V, C0G, ±0.1pF, SMD 0603; Manufacturer: FH(Guangdong Fenghua Advanced Tech); Manufacturer Part Number: 0603CG7R0B500NT
footprint CAP-0603 (0603 (1608M) Capacitor)
pins: 1, 2

## 0603CG7R0C500NT
designator C?  Capacitance: 7pF  (hidden comment: *)
Capacitor, Ceramic (MLCC), 7pF, ±0.25pF, 50V, C0G, ±0.25pF, SMD 0603; Manufacturer: FH(Guangdong Fenghua Advanced Tech); Manufacturer Part Number: 0603CG7R0C500NT
footprint CAP-0603 (0603 (1608M) Capacitor)
pins: 1, 2

## 0603CG7R5C101NT
designator C?  Capacitance: 7.5pF  (hidden comment: *)
Capacitor, Ceramic (MLCC), 7.5pF, ±0.25pF, 100V, C0G, ±0.25pF, SMD 0603; Manufacturer: FH(Guangdong Fenghua Advanced Tech); Manufacturer Part Number: 0603CG7R5C101NT
footprint CAP-0603 (0603 (1608M) Capacitor)
pins: 1, 2

## 0603CG7R5C500NT
designator C?  Capacitance: 7.5pF  (hidden comment: *)
Capacitor, Ceramic (MLCC), 7.5pF, ±0.25pF, 50V, C0G, ±0.25pF, SMD 0603; Manufacturer: FH(Guangdong Fenghua Advanced Tech); Manufacturer Part Number: 0603CG7R5C500NT
footprint CAP-0603 (0603 (1608M) Capacitor)
pins: 1, 2

## 0603CG8R0C101NT
designator C?  Capacitance: 8pF  (hidden comment: *)
Capacitor, Ceramic (MLCC), 8pF, ±0.25pF, 100V, C0G, ±0.25pF, SMD 0603; Manufacturer: FH(Guangdong Fenghua Advanced Tech); Manufacturer Part Number: 0603CG8R0C101NT
footprint CAP-0603 (0603 (1608M) Capacitor)
pins: 1, 2

## 0603CG8R0C500NT
designator C?  Capacitance: 8pF  (hidden comment: *)
Capacitor, Ceramic (MLCC), 8pF, ±0.25pF, 50V, C0G, ±0.25pF, SMD 0603; Manufacturer: FH(Guangdong Fenghua Advanced Tech); Manufacturer Part Number: 0603CG8R0C500NT
footprint CAP-0603 (0603 (1608M) Capacitor)
pins: 1, 2

## 0603CG8R2B500NT
designator C?  Capacitance: 8.2pF  (hidden comment: *)
Capacitor, Ceramic (MLCC), 8.2pF, ±0.1pF, 50V, ±0.1pF, SMD 0603; Manufacturer: FH(Guangdong Fenghua Advanced Tech); Manufacturer Part Number: 0603CG8R2B500NT
footprint CAP-0603 (0603 (1608M) Capacitor)
pins: 1, 2

## 0603CG8R2D500NT
designator C?  Capacitance: 8.2pF  (hidden comment: *)
Capacitor, Ceramic (MLCC), 8.2pF, ±0.5pF, 50V, C0G, ±0.5pF, SMD 0603; Manufacturer: FH(Guangdong Fenghua Advanced Tech); Manufacturer Part Number: 0603CG8R2D500NT
footprint CAP-0603 (0603 (1608M) Capacitor)
pins: 1, 2

## 0603CG8R5C500NT
designator C?  Capacitance: 8.5pF  (hidden comment: *)
Capacitor, Ceramic (MLCC), 8.5pF, ±0.25pF, 50V, C0G, ±0.25pF, SMD 0603; Manufacturer: FH(Guangdong Fenghua Advanced Tech); Manufacturer Part Number: 0603CG8R5C500NT
footprint CAP-0603 (0603 (1608M) Capacitor)
pins: 1, 2

## 0603CG9R1C500NT
designator C?  Capacitance: 9.1pF  (hidden comment: *)
Capacitor, Ceramic (MLCC), 9.1pF, ±0.25pF, 50V, C0G, ±0.25pF, SMD 0603; Manufacturer: FH(Guangdong Fenghua Advanced Tech); Manufacturer Part Number: 0603CG9R1C500NT
footprint CAP-0603 (0603 (1608M) Capacitor)
pins: 1, 2

## 0603CG100D500NT
designator C?  Capacitance: 10pF  (hidden comment: *)
Capacitor, Ceramic (MLCC), 10pF, ±0.5pF, 50V, C0G, ±0.5pF, SMD 0603; Manufacturer: FH(Guangdong Fenghua Advanced Tech); Manufacturer Part Number: 0603CG100D500NT
footprint CAP-0603 (0603 (1608M) Capacitor)
pins: 1, 2

## 0603CG100G500NT
designator C?  Capacitance: 10pF  (hidden comment: *)
Capacitor, Ceramic (MLCC), 10pF, ±2%, 50V, C0G, ±2%, SMD 0603; Manufacturer: FH(Guangdong Fenghua Advanced Tech); Manufacturer Part Number: 0603CG100G500NT
footprint CAP-0603 (0603 (1608M) Capacitor)
pins: 1, 2

## 0603CG100J101NT
designator C?  Capacitance: 10pF  (hidden comment: *)
Capacitor, Ceramic (MLCC), 10pF, ±5%, 100V, C0G, ±5%, SMD 0603; Manufacturer: FH(Guangdong Fenghua Advanced Tech); Manufacturer Part Number: 0603CG100J101NT
footprint CAP-0603 (0603 (1608M) Capacitor)
pins: 1, 2

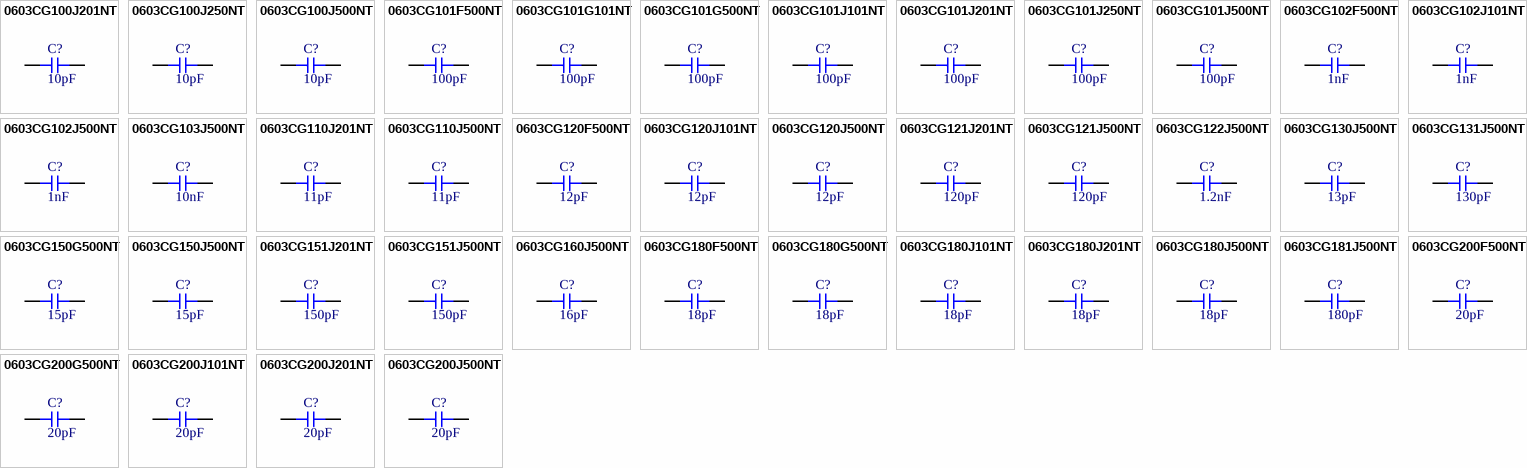
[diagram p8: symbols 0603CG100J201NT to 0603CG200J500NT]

## 0603CG100J201NT
designator C?  Capacitance: 10pF  (hidden comment: *)
Capacitor, Ceramic (MLCC), 10pF, ±5%, 200V, C0G, ±5%, SMD 0603; Manufacturer: FH(Guangdong Fenghua Advanced Tech); Manufacturer Part Number: 0603CG100J201NT
footprint CAP-0603 (0603 (1608M) Capacitor)
pins: 1, 2

## 0603CG100J250NT
designator C?  Capacitance: 10pF  (hidden comment: *)
Capacitor, Ceramic (MLCC), 10pF, ±5%, 25V, C0G, ±5%, SMD 0603; Manufacturer: FH (Guangdong Fenghua Advanced Tech); Manufacturer Part Number: 0603CG100J250NT
footprint CAP-0603 (0603 (1608M) Capacitor)
pins: 1, 2

## 0603CG100J500NT
designator C?  Capacitance: 10pF  (hidden comment: *)
Capacitor, Ceramic (MLCC), 10pF, ±5%, 50V, C0G, ±5%, SMD 0603; Manufacturer: FH(Guangdong Fenghua Advanced Tech); Manufacturer Part Number: 0603CG100J500NT
footprint CAP-0603 (0603 (1608M) Capacitor)
pins: 1, 2

## 0603CG101F500NT
designator C?  Capacitance: 100pF  (hidden comment: *)
Capacitor, Ceramic (MLCC), 100pF, ±1%, 50V, C0G, ±1%, SMD 0603; Manufacturer: FH(Guangdong Fenghua Advanced Tech); Manufacturer Part Number: 0603CG101F500NT
footprint CAP-0603 (0603 (1608M) Capacitor)
pins: 1, 2

## 0603CG101G101NT
designator C?  Capacitance: 100pF  (hidden comment: *)
Capacitor, Ceramic (MLCC), 100pF, ±2%, 100V, C0G, ±2%, SMD 0603; Manufacturer: FH(Guangdong Fenghua Advanced Tech); Manufacturer Part Number: 0603CG101G101NT
footprint CAP-0603 (0603 (1608M) Capacitor)
pins: 1, 2

## 0603CG101G500NT
designator C?  Capacitance: 100pF  (hidden comment: *)
Capacitor, Ceramic (MLCC), 100pF, ±2%, 50V, C0G, ±2%, SMD 0603; Manufacturer: FH(Guangdong Fenghua Advanced Tech); Manufacturer Part Number: 0603CG101G500NT
footprint CAP-0603 (0603 (1608M) Capacitor)
pins: 1, 2

## 0603CG101J101NT
designator C?  Capacitance: 100pF  (hidden comment: *)
Capacitor, Ceramic (MLCC), 100pF, ±5%, 100V, C0G, ±5%, SMD 0603; Manufacturer: FH(Guangdong Fenghua Advanced Tech); Manufacturer Part Number: 0603CG101J101NT
footprint CAP-0603 (0603 (1608M) Capacitor)
pins: 1, 2

## 0603CG101J201NT
designator C?  Capacitance: 100pF  (hidden comment: *)
Capacitor, Ceramic (MLCC), 100pF, ±5%, 200V, C0G, ±5%, SMD 0603; Manufacturer: FH(Guangdong Fenghua Advanced Tech); Manufacturer Part Number: 0603CG101J201NT
footprint CAP-0603 (0603 (1608M) Capacitor)
pins: 1, 2

## 0603CG101J250NT
designator C?  Capacitance: 100pF  (hidden comment: *)
Capacitor, Ceramic (MLCC), 100pF, ±5%, 25V, C0G, ±5%, SMD 0603; Manufacturer: FH(Guangdong Fenghua Advanced Tech); Manufacturer Part Number: 0603CG101J250NT
footprint CAP-0603 (0603 (1608M) Capacitor)
pins: 1, 2

## 0603CG101J500NT
designator C?  Capacitance: 100pF  (hidden comment: *)
Capacitor, Ceramic (MLCC), 100pF, ±5%, 50V, C0G, ±5%, SMD 0603; Manufacturer: FH(Guangdong Fenghua Advanced Tech); Manufacturer Part Number: 0603CG101J500NT
footprint CAP-0603 (0603 (1608M) Capacitor)
pins: 1, 2

## 0603CG102F500NT
designator C?  Capacitance: 1nF  (hidden comment: *)
Capacitor, Ceramic (MLCC), 1nF, ±1%, 50V, C0G, ±1%, SMD 0603; Manufacturer: FH(Guangdong Fenghua Advanced Tech); Manufacturer Part Number: 0603CG102F500NT
footprint CAP-0603 (0603 (1608M) Capacitor)
pins: 1, 2

## 0603CG102J101NT
designator C?  Capacitance: 1nF  (hidden comment: *)
Capacitor, Ceramic (MLCC), 1nF, ±5%, 100V, C0G, ±5%, SMD 0603; Manufacturer: FH(Guangdong Fenghua Advanced Tech); Manufacturer Part Number: 0603CG102J101NT
footprint CAP-0603 (0603 (1608M) Capacitor)
pins: 1, 2

## 0603CG102J500NT
designator C?  Capacitance: 1nF  (hidden comment: *)
Capacitor, Ceramic (MLCC), 1nF, ±5%, 50V, C0G, ±5%, SMD 0603; Manufacturer: FH(Guangdong Fenghua Advanced Tech); Manufacturer Part Number: 0603CG102J500NT
footprint CAP-0603 (0603 (1608M) Capacitor)
pins: 1, 2

## 0603CG103J500NT
designator C?  Capacitance: 10nF  (hidden comment: *)
Capacitor, Ceramic (MLCC), 10nF, ±5%, 50V, C0G, ±5%, SMD 0603; Manufacturer: FH(Guangdong Fenghua Advanced Tech); Manufacturer Part Number: 0603CG103J500NT
footprint CAP-0603 (0603 (1608M) Capacitor)
pins: 1, 2

## 0603CG110J201NT
designator C?  Capacitance: 11pF  (hidden comment: *)
Capacitor, Ceramic (MLCC), 11pF, ±5%, 200V, C0G, ±5%, SMD 0603; Manufacturer: FH(Guangdong Fenghua Advanced Tech); Manufacturer Part Number: 0603CG110J201NT
footprint CAP-0603 (0603 (1608M) Capacitor)
pins: 1, 2

## 0603CG110J500NT
designator C?  Capacitance: 11pF  (hidden comment: *)
Capacitor, Ceramic (MLCC), 11pF, ±5%, 50V, C0G, ±5%, SMD 0603; Manufacturer: FH(Guangdong Fenghua Advanced Tech); Manufacturer Part Number: 0603CG110J500NT
footprint CAP-0603 (0603 (1608M) Capacitor)
pins: 1, 2

## 0603CG120F500NT
designator C?  Capacitance: 12pF  (hidden comment: *)
Capacitor, Ceramic (MLCC), 12pF, ±1%, 50V, C0G, ±1%, SMD 0603; Manufacturer: FH(Guangdong Fenghua Advanced Tech); Manufacturer Part Number: 0603CG120F500NT
footprint CAP-0603 (0603 (1608M) Capacitor)
pins: 1, 2

## 0603CG120J101NT
designator C?  Capacitance: 12pF  (hidden comment: *)
Capacitor, Ceramic (MLCC), 12pF, ±5%, 100V, C0G, ±5%, SMD 0603; Manufacturer: FH(Guangdong Fenghua Advanced Tech); Manufacturer Part Number: 0603CG120J101NT
footprint CAP-0603 (0603 (1608M) Capacitor)
pins: 1, 2

## 0603CG120J500NT
designator C?  Capacitance: 12pF  (hidden comment: *)
Capacitor, Ceramic (MLCC), 12pF, ±5%, 50V, C0G, ±5%, SMD 0603; Manufacturer: FH(Guangdong Fenghua Advanced Tech); Manufacturer Part Number: 0603CG120J500NT
footprint CAP-0603 (0603 (1608M) Capacitor)
pins: 1, 2

## 0603CG121J201NT
designator C?  Capacitance: 120pF  (hidden comment: *)
Capacitor, Ceramic (MLCC), 120pF, ±5%, 200V, C0G, ±5%, SMD 0603; Manufacturer: FH(Guangdong Fenghua Advanced Tech); Manufacturer Part Number: 0603CG121J201NT
footprint CAP-0603 (0603 (1608M) Capacitor)
pins: 1, 2

## 0603CG121J500NT
designator C?  Capacitance: 120pF  (hidden comment: *)
Capacitor, Ceramic (MLCC), 120pF, ±5%, 50V, C0G, ±5%, SMD 0603; Manufacturer: FH(Guangdong Fenghua Advanced Tech); Manufacturer Part Number: 0603CG121J500NT
footprint CAP-0603 (0603 (1608M) Capacitor)
pins: 1, 2

## 0603CG122J500NT
designator C?  Capacitance: 1.2nF  (hidden comment: *)
Capacitor, Ceramic (MLCC), 1.2nF, ±5%, 50V, C0G, ±5%, SMD 0603; Manufacturer: FH(Guangdong Fenghua Advanced Tech); Manufacturer Part Number: 0603CG122J500NT
footprint CAP-0603 (0603 (1608M) Capacitor)
pins: 1, 2

## 0603CG130J500NT
designator C?  Capacitance: 13pF  (hidden comment: *)
Capacitor, Ceramic (MLCC), 13pF, ±5%, 50V, C0G, ±5%, SMD 0603; Manufacturer: FH(Guangdong Fenghua Advanced Tech); Manufacturer Part Number: 0603CG130J500NT
footprint CAP-0603 (0603 (1608M) Capacitor)
pins: 1, 2

## 0603CG131J500NT
designator C?  Capacitance: 130pF  (hidden comment: *)
Capacitor, Ceramic (MLCC), 130pF, ±5%, 50V, C0G, ±5%, SMD 0603; Manufacturer: FH(Guangdong Fenghua Advanced Tech); Manufacturer Part Number: 0603CG131J500NT
footprint CAP-0603 (0603 (1608M) Capacitor)
pins: 1, 2

## 0603CG150G500NT
designator C?  Capacitance: 15pF  (hidden comment: *)
Capacitor, Ceramic (MLCC), 15pF, ±2%, 50V, ±2%, SMD 0603; Manufacturer: FH (Guangdong Fenghua Advanced Tech); Manufacturer Part Number: 0603CG150G500NT
footprint CAP-0603 (0603 (1608M) Capacitor)
pins: 1, 2

## 0603CG150J500NT
designator C?  Capacitance: 15pF  (hidden comment: *)
Capacitor, Ceramic (MLCC), 15pF, ±5%, 50V, C0G, ±5%, SMD 0603; Manufacturer: FH(Guangdong Fenghua Advanced Tech); Manufacturer Part Number: 0603CG150J500NT
footprint CAP-0603 (0603 (1608M) Capacitor)
pins: 1, 2

## 0603CG151J201NT
designator C?  Capacitance: 150pF  (hidden comment: *)
Capacitor, Ceramic (MLCC), 150pF, ±5%, 200V, C0G, ±5%, SMD 0603; Manufacturer: FH(Guangdong Fenghua Advanced Tech); Manufacturer Part Number: 0603CG151J201NT
footprint CAP-0603 (0603 (1608M) Capacitor)
pins: 1, 2

## 0603CG151J500NT
designator C?  Capacitance: 150pF  (hidden comment: *)
Capacitor, Ceramic (MLCC), 150pF, ±5%, 50V, C0G, ±5%, SMD 0603; Manufacturer: FH(Guangdong Fenghua Advanced Tech); Manufacturer Part Number: 0603CG151J500NT
footprint CAP-0603 (0603 (1608M) Capacitor)
pins: 1, 2

## 0603CG160J500NT
designator C?  Capacitance: 16pF  (hidden comment: *)
Capacitor, Ceramic (MLCC), 16pF, ±5%, 50V, C0G, ±5%, SMD 0603; Manufacturer: FH(Guangdong Fenghua Advanced Tech); Manufacturer Part Number: 0603CG160J500NT
footprint CAP-0603 (0603 (1608M) Capacitor)
pins: 1, 2

## 0603CG180F500NT
designator C?  Capacitance: 18pF  (hidden comment: *)
Capacitor, Ceramic (MLCC), 18pF, ±1%, 50V, C0G, ±1%, SMD 0603; Manufacturer: FH(Guangdong Fenghua Advanced Tech); Manufacturer Part Number: 0603CG180F500NT
footprint CAP-0603 (0603 (1608M) Capacitor)
pins: 1, 2

## 0603CG180G500NT
designator C?  Capacitance: 18pF  (hidden comment: *)
Capacitor, Ceramic (MLCC), 18pF, ±2%, 50V, C0G, ±2%, SMD 0603; Manufacturer: FH(Guangdong Fenghua Advanced Tech); Manufacturer Part Number: 0603CG180G500NT
footprint CAP-0603 (0603 (1608M) Capacitor)
pins: 1, 2

## 0603CG180J101NT
designator C?  Capacitance: 18pF  (hidden comment: *)
Capacitor, Ceramic (MLCC), 18pF, ±5%, 100V, ±5%, SMD 0603; Manufacturer: FH(Guangdong Fenghua Advanced Tech); Manufacturer Part Number: 0603CG180J101NT
footprint CAP-0603 (0603 (1608M) Capacitor)
pins: 1, 2

## 0603CG180J201NT
designator C?  Capacitance: 18pF  (hidden comment: *)
Capacitor, Ceramic (MLCC), 18pF, ±5%, 200V, C0G, ±5%, SMD 0603; Manufacturer: FH(Guangdong Fenghua Advanced Tech); Manufacturer Part Number: 0603CG180J201NT
footprint CAP-0603 (0603 (1608M) Capacitor)
pins: 1, 2

## 0603CG180J500NT
designator C?  Capacitance: 18pF  (hidden comment: *)
Capacitor, Ceramic (MLCC), 18pF, ±5%, 50V, C0G, ±5%, SMD 0603; Manufacturer: FH(Guangdong Fenghua Advanced Tech); Manufacturer Part Number: 0603CG180J500NT
footprint CAP-0603 (0603 (1608M) Capacitor)
pins: 1, 2

## 0603CG181J500NT
designator C?  Capacitance: 180pF  (hidden comment: *)
Capacitor, Ceramic (MLCC), 180pF, ±5%, 50V, C0G, ±5%, SMD 0603; Manufacturer: FH(Guangdong Fenghua Advanced Tech); Manufacturer Part Number: 0603CG181J500NT
footprint CAP-0603 (0603 (1608M) Capacitor)
pins: 1, 2

## 0603CG200F500NT
designator C?  Capacitance: 20pF  (hidden comment: *)
Capacitor, Ceramic (MLCC), 20pF, ±1%, 50V, C0G, ±1%, SMD 0603; Manufacturer: FH(Guangdong Fenghua Advanced Tech); Manufacturer Part Number: 0603CG200F500NT
footprint CAP-0603 (0603 (1608M) Capacitor)
pins: 1, 2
